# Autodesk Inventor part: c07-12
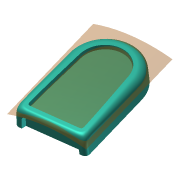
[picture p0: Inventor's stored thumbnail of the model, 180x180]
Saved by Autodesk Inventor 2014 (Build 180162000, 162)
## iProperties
Created: 2010-12
Part Number: c07-12
Material: Generic
Document SubType Name: Modeling
Designer: Thom Tremblay
Density: 1 g/cm^3
Appearance: Smooth - Aqua
Author: Thom Tremblay
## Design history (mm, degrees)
sketch "Sketch1"
  geometry: L1 (-25, 0)-(25, 0); L2 (25, 0)-(25, 80); L3 (25, 80)-(-25, 80); L4 (-25, 80)-(-25, 0); 2 further points
  constraints: 8 end point, 2 parallel, 1 coincident, 1 horizontal, 1 midpoint, 1 perpendicular
  dimensions: "d0" = 50 distance of L3.end L2.end; "d1" = 80 distance of L2.end L1.end
extrude "Extrusion1" new body sketch "Sketch1" distance "d2" = 15; taper "d3" = 0 deg
feature "FaceDraft1" dims angle "d4" = -2 deg
fillet "Fillet1"
fillet "Fillet2" dims "d5" = 8, "d6" = 8, "d7" = 8, "d8" = 8, "d9" = 8, "d10" = 8, "d11" = 3, "d12" = 3, "d13" = 3, "d14" = 6, "d15" = 5
sketch "Sketch2"
  geometry: L1 (5.522, 12)-(38.474, 12) reference; L2 (0, 0)-(43.996, 0) reference; L3 (41.757, 6.83)-(41.995, 0); L4 (41.925, 2)-(2.071, 2); L5 (2.001, 0)-(2.24, 6.83); L6 (5.522, 10)-(38.474, 10); A1 r 5.284 centre (38.474, 6.716) between (43.755, 6.9) and (38.474, 12) reference; A2 r 5.284 centre (5.522, 6.716) between (5.522, 12) and (0.241, 6.9) reference; A3 r 3.284 centre (38.474, 6.716) between (41.757, 6.83) and (38.474, 10); A4 r 3.284 centre (5.522, 6.716) between (5.522, 10) and (2.24, 6.83); 1 further point
  constraints: 8 end point, 4 point on circle, 4 point on line, 2 centre point, 1 other
  dimensions: "d16" = 2 radial gap between concentric circles of A2 A4
extrude "Extrusion2" cut sketch "Sketch2" distance "d17" = 3; taper "d18" = 0 deg
feature "FaceDraft2" dims angle "d19" = 15 deg
sketch "Sketch3" dims "d20" = 2.5
  geometry: L1 (16.476, 3)-(-16.476, 3) reference; L2 (16.476, 5.5)-(-16.476, 5.5); 9 further points
  constraints: 2 end point, 2 parallel, 1 horizontal alignment, 19 other
extrude "Extrusion3" cut sketch "Sketch3" distance "d21" = 3; taper "d22" = 0 deg
feature "FaceDraft3" dims angle "d23" = 10 deg
workplane "Work Plane1"
sketch "Sketch4"
  geometry: L1 (41.1, -1.222)-(41.476, -12) reference; L2 (41.476, -12)-(-8.524, -12) reference; L3 (-8.524, -12)-(-8.147, -1.222) reference; L4 (-3.776, 3)-(-1.272, 3) reference; L5 (-0.743, 0)-(33.695, 0) reference; L6 (34.225, 3)-(36.728, 3) reference; L7 (-11.024, -1.804)-(43.976, -1.804); A1 r 90 centre (16.476, -87.5) between (43.976, -1.804) and (-11.024, -1.804); 2 further points
  constraints: 2 end point, 2 point on circle, 1 centre point, 1 midpoint, 1 parallel, 1 vertical alignment, 4 other
  dimensions: "d25" = 90 radius of A1; "d26" = 14.5 distance edge to line of A1 L2; "d27" = 55 distance of L7.start L7.end
extrude_surface "ExtrusionSrf1" sketch "Sketch4" dims "d28" = 86, "d29" = 0
body "Solid1"
body "Srf1"
node "Project Cut Edges1"
